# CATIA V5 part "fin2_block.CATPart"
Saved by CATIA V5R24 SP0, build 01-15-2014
Part number: Frame Left
Bounding box of the stored display mesh (mm): x -8.75 to 1.25, y 0 to 25, z 0 to 31.822
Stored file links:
  G:\내 드라이브\04_WORK\00_LECTURE\CAD2020\exam\fin2_block.CATPart
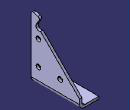
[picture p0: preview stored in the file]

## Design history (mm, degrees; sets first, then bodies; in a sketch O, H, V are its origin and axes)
Body1 (main body)
  Sketch1 on yz-plane, origin (0, 0, 0), H (0, 1, 0), V (0, 0, 1)
    line L1 (0, 0) -> (0, 32.1879)
    point P3 (4, 26.5)
    line L2 (2.6431, 27.3479) -> (4.8063, 30.8097)
    line L3 (4.8534, 25.1466) -> (25, 5)
    point P6 (25, 5)
    line L4 (25, 5) -> (25, 0)
    point P7 (25, 5)
    point P8 (25, 0)
    line L5 (25, 0) -> (0, 0)
    circle A1 centre (3.75, 8.75) radius 1.25
    point P9 (3.75, 8.75)
    circle A2 centre (15, 8.75) radius 1.25
    point P10 (15, 8.75)
    circle A3 centre (3.75, 21.25) radius 1.25
    point P11 (3.75, 21.25)
    arc A4 centre (4, 26.5) radius 1.6 from (2.6431, 27.3479) to (4.8534, 25.1466) ccw
    line L6 (0, 32.1879) -> (4.8063, 30.8097)
    length L5 = 25
    length L4 = 5
    radius A1 = 1.25
    radius A2 = 1.25
    radius A3 = 1.25
    radius A4 = 1.6
    angle L2 L1 = 32
    angle L1 L6 = 74
    distance P3 V = 4
    distance P11 L1 = 3.75
    distance P9 L1 = 3.75
    angle L3 H = 45
    distance P9 L5 = 8.75
    distance P10 L5 = 8.75
    distance P10 L1 = 15
    distance P11 L5 = 21.25
    distance P3 L5 = 26.5
    length L6 = 5
    vertical: L1 V, L4 V
    coincidence: P7 L3, P8 H, P6 P7
    horizontal: L5 H
    tangency: A4 L2
  Pad1: profile Sketch1, direction (1, 0, 0), length 1.25
  Sketch2 on face of Pad1 from Sketch1.L4, origin (0, 25, 0), H (-1, 0, 0), V (0, 0, 1)
    point P2 (-1.25, 0)
    projected line E2 (0, 0) -> (0, 5) from edge [start face of Pad1 | face of Pad1 from Sketch1.L4]
    projected line E3 (0, 0) -> (0, 1.25) from edge [start face of Pad1 | face of Pad1 from Sketch1.L4]
    line L1 (0, 0) -> (8.75, 0)
    line L2 (8.75, 0) -> (8.75, 1.25)
    line L3 (8.75, 1.25) -> (0, 1.25)
    point P7 (0, 1.25)
    construction line L4 (0, 1.25) -> (0, 0)
    distance P2 L2 = 10
    length L2 = 1.25
    horizontal: L1 H, L3 H
    vertical: L2 V, L4 V
    coincidence: P7 E2
  Pad2: profile Sketch2, direction (0, -1, 0), length 25
  Fillet1: radius 1.5, on edge [face of Pad2 from Sketch2.L3 | start face of Pad1]
  Fillet2: radius 2.5, on edge [face of Pad2 | end face of Pad1]
  Fillet3: radius 1, on edge [face of Pad1 from Sketch1.L6 | face of Pad1 from Sketch1.L2]; edge [face of Pad2 | face of Pad1 from Sketch1.L6]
